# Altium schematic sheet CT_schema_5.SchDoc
size 371 x 245 mm
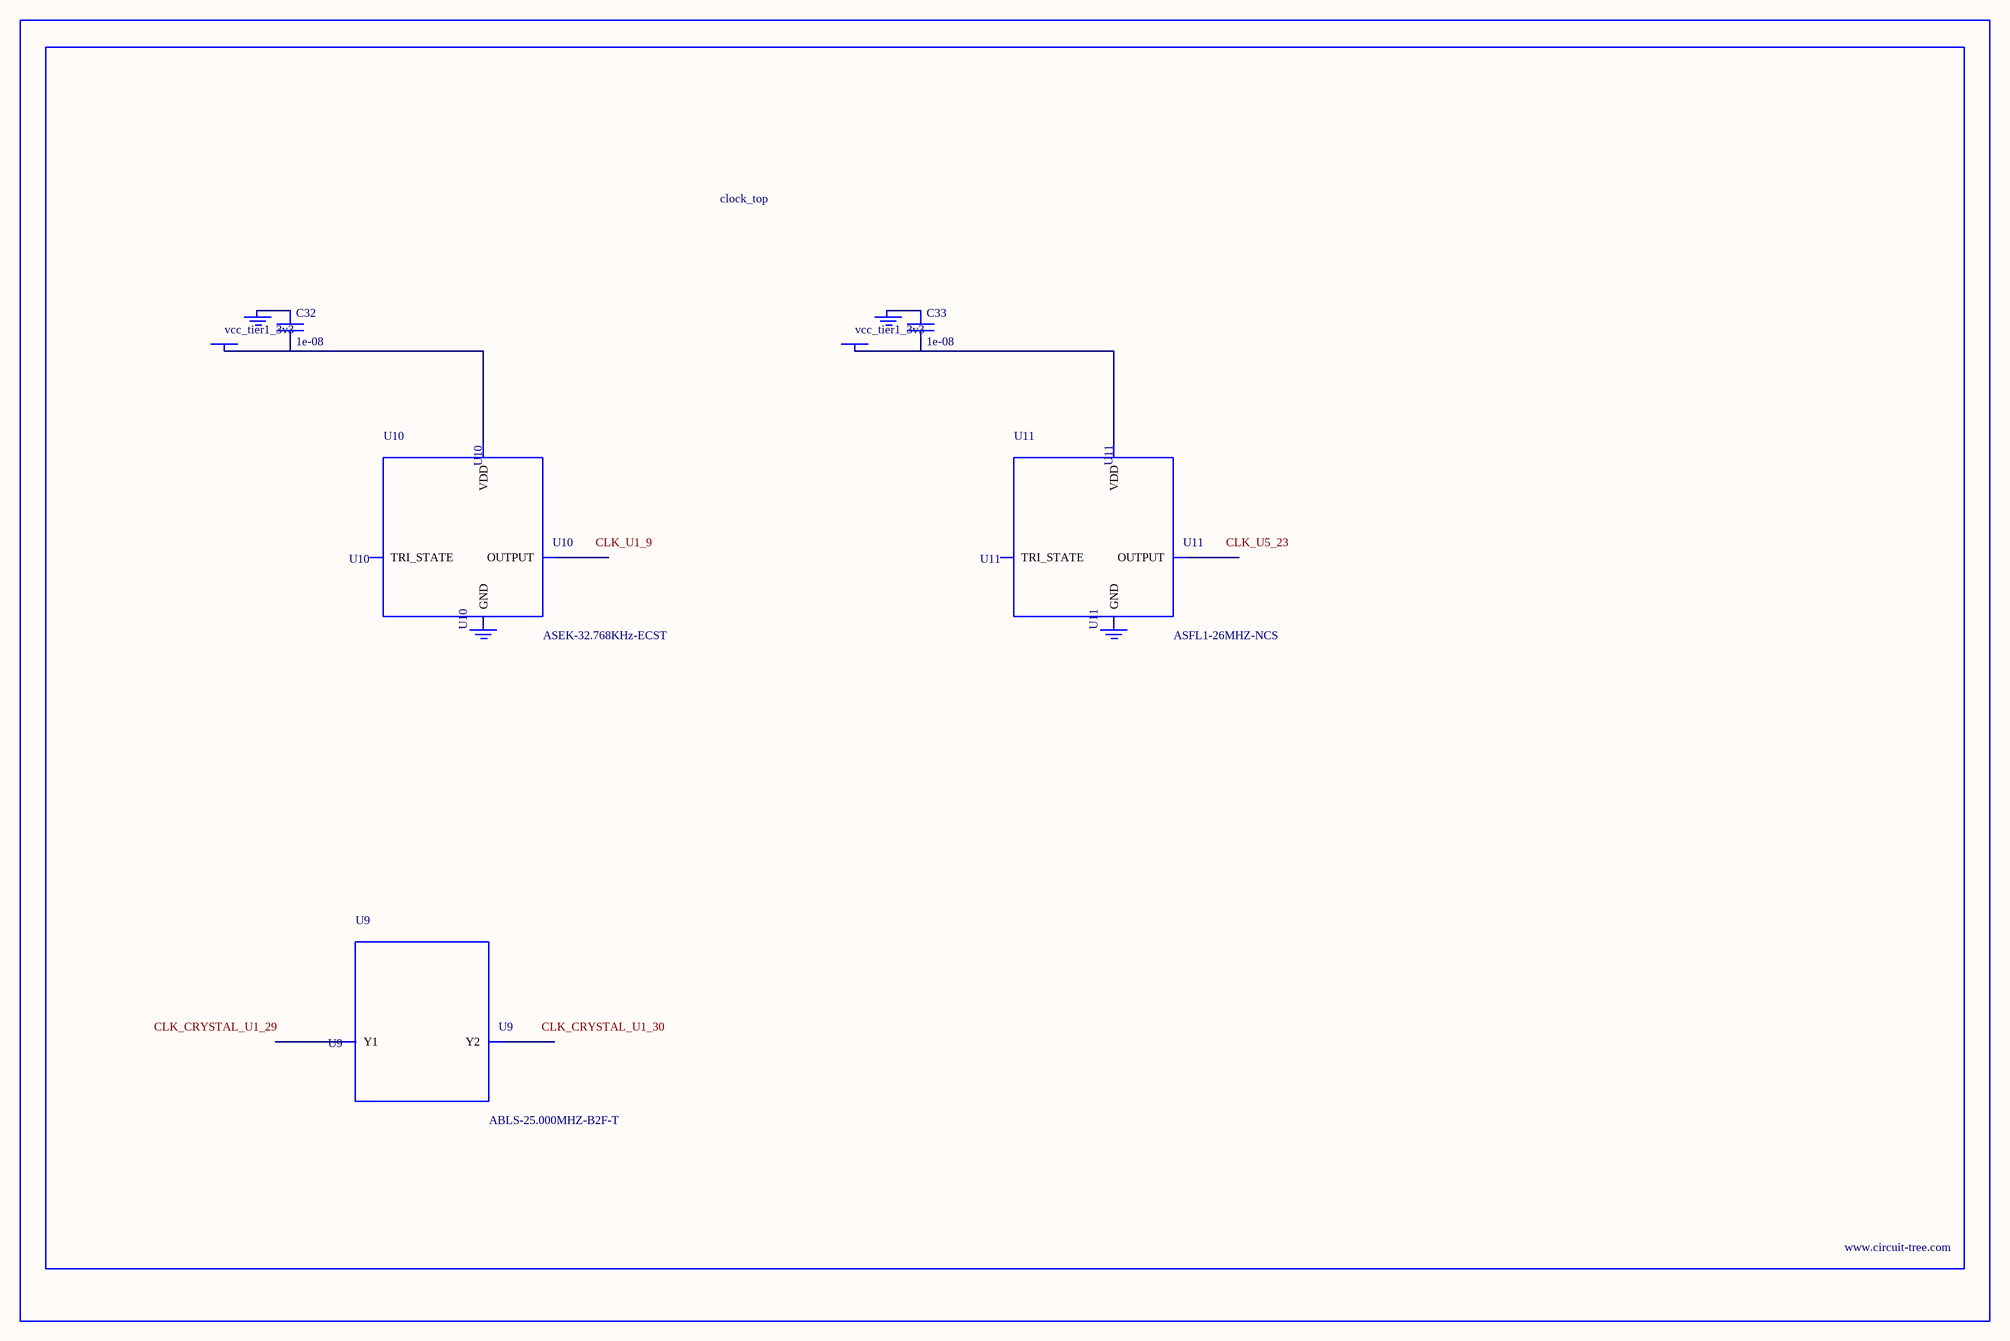
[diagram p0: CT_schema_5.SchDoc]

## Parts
BORDER4  (no value)
C32  1e-08  [C0402]
C33  1e-08  [C0402]
GND_INSTANCE_4_0  (no value)
GND_INSTANCE_4_1  (no value)
GND_INSTANCE_4_2  (no value)
GND_INSTANCE_4_3  (no value)
POWER_INSTANCE_4_0  vcc_tier1_3v3
POWER_INSTANCE_4_1  vcc_tier1_3v3
U9  ABLS-25.000MHZ-B2F-T  [ABLS-25.000MHZ-B2F-T]
U10  ASEK-32.768KHz-ECST  [ASEK]
U11  ASFL1-26MHZ-NCS  [ASFL1]

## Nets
NetC32_1: C32.1 GND_INSTANCE_4_0.0(GND)
NetC32_2: C32.2 POWER_INSTANCE_4_0.0(PWR) U10.4(VDD)
NetC33_1: C33.1 GND_INSTANCE_4_2.0(GND)
NetC33_2: C33.2 POWER_INSTANCE_4_1.0(PWR) U11.4(VDD)

Not connected (* = marked no-connect by the designer): GND_INSTANCE_4_1 0(GND); GND_INSTANCE_4_3 0(GND); U9 1(Y1) 2(Y2); U10 1(TRI_STATE) 2(GND) 3(OUTPUT); U11 1(TRI_STATE) 2(GND) 3(OUTPUT)

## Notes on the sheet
- Labels drawn without touching a wire or pin: CLK_CRYSTAL_U1_29, CLK_CRYSTAL_U1_30, CLK_U1_9, CLK_U5_23

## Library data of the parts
BORDER4 = BORDER_PAGE4
C32 C33 = C0402C103K3RAC
GND_INSTANCE_4_0-GND_INSTANCE_4_3 = GND
POWER_INSTANCE_4_0 POWER_INSTANCE_4_1 = PWR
